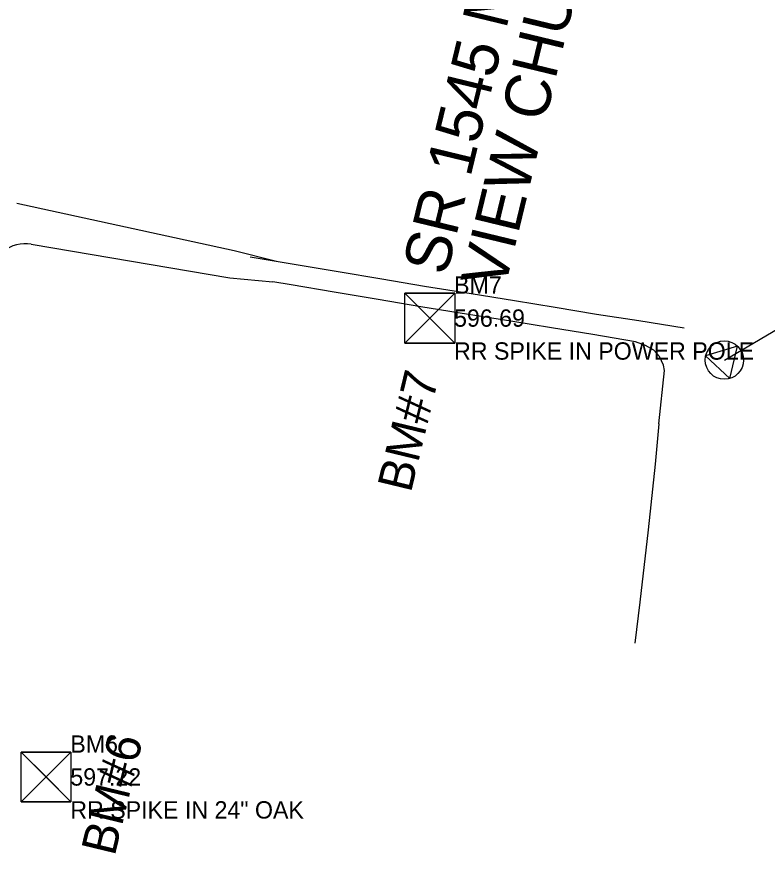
# Model space of a CAD drawing. Extents: x 1649669 to 1659218, y 588594 to 607900.
# Drawn here: x 1655167 to 1656033, y 600426 to 601392 of the extents above; entities that cross this region are included whole.
import ezdxf

# ---------------------------------------------------------------- set-up
doc = ezdxf.new("R2010")
doc.units = 0
for name, color, linetype in [('CTL Bench Mark CELL', 7, 'Continuous'), ('CTL Bench Mark Cogo Comment', 7, 'Continuous'), ('CTL Bench Mark Cogo Elevation', 7, 'Continuous'), ('CTL Bench Mark Cogo Number', 7, 'Continuous'), ('CTL Bench Mark Text', 7, 'Continuous'), ('CTL NGS Horizontal CELL', 7, 'Continuous'), ('CTL NGS Horizontal Leader', 7, 'Continuous'), ('Exist Roads EOP', 7, 'Continuous'), ('Sheet Data Field CELL', 7, 'Continuous')]:
    doc.layers.add(name, color=color, linetype=linetype)

# ---------------------------------------------------------------- blocks, each defined once
blk = doc.blocks.new('CTL NGS HORIZONTAL')
at = {"layer": 'CTL NGS Horizontal CELL'}
blk.add_line((0, 0), (0, 0), dxfattribs=at)
blk.add_lwpolyline([(-0.0638, -0.0372), (0.0638, -0.0372), (0, 0.0737), (-0.0638, -0.0372)], dxfattribs=at)
blk.add_circle((0, 0), 0.0738, dxfattribs=at)

msp = doc.modelspace()

# ---------------------------------------------------------------- linework, layer by layer
at = {"layer": 'CTL Bench Mark CELL'}
for p, q in [((1655643.59, 601043.97), (1655643.59, 601043.97)), ((1655200.64, 600514.48), (1655200.64, 600514.48))]:
    msp.add_line(p, q, dxfattribs=at)
for points in [[(1655614.79, 601072.67), (1655672.29, 601072.67), (1655672.29, 601015.17), (1655614.79, 601015.17)], [(1655171.84, 600543.18), (1655229.34, 600543.18), (1655229.34, 600485.68), (1655171.84, 600485.68)]]:
    msp.add_lwpolyline(points, close=True, dxfattribs=at)
for points in [[(1655672.29, 601072.67), (1655614.79, 601015.17), (1655643.54, 601043.92), (1655672.29, 601015.17), (1655614.79, 601072.67)], [(1655643.54, 601043.92), (1655672.29, 601072.67), (1655614.79, 601072.67), (1655643.54, 601043.92)], [(1655643.54, 601043.92), (1655614.79, 601015.17), (1655672.29, 601015.17), (1655643.54, 601043.92)], [(1655229.34, 600543.18), (1655171.84, 600485.68), (1655200.59, 600514.43), (1655229.34, 600485.68), (1655171.84, 600543.18)], [(1655200.59, 600514.43), (1655229.34, 600543.18), (1655171.84, 600543.18), (1655200.59, 600514.43)], [(1655200.59, 600514.43), (1655171.84, 600485.68), (1655229.34, 600485.68), (1655200.59, 600514.43)]]:
    msp.add_lwpolyline(points, dxfattribs=at)
at = {"layer": 'CTL NGS Horizontal Leader'}
msp.add_lwpolyline([(1655983.6, 600995.47), (1656243.85, 601148.6), (1656234.63, 601110.4)], dxfattribs=at)
at = {"layer": 'Exist Roads EOP'}
for p, q in [((1655166.87, 601176.61), (1655417.93, 601121.93)), ((1655183.46, 601129.18), (1655412.59, 601090.37)), ((1655417.93, 601121.92), (1655466.54, 601109.51)), ((1655436.39, 601114.75), (1655486.96, 601105.97)), ((1655486.96, 601105.97), (1655537.77, 601097.66)), ((1655537.77, 601097.66), (1655588.14, 601089.12)), ((1655412.59, 601090.37), (1655462.55, 601085.95)), ((1655483.44, 601082.33), (1655462.55, 601085.95)), ((1655533.01, 601073.9), (1655483.44, 601082.33)), ((1655588.14, 601089.12), (1655637.54, 601080.83)), ((1655637.54, 601080.83), (1655691.21, 601072.26)), ((1655584.06, 601065.32), (1655533.01, 601073.9)), ((1655691.21, 601072.26), (1655741.32, 601064.15)), ((1655633.1, 601056.94), (1655584.06, 601065.32)), ((1655741.32, 601064.15), (1655788.25, 601056.36)), ((1655688.16, 601048.1), (1655633.1, 601056.94)), ((1655788.25, 601056.36), (1655836, 601048.61)), ((1655737.3, 601040.21), (1655688.16, 601048.1)), ((1655836, 601048.61), (1655884.72, 601040.96)), ((1655783.97, 601032.62), (1655737.3, 601040.21)), ((1655831.74, 601024.99), (1655783.97, 601032.62)), ((1655884.72, 601040.96), (1655937.31, 601032.79)), ((1655881.18, 601016.56), (1655831.74, 601024.99)), ((1655892.38, 601012.38), (1655881.18, 601016.56)), ((1655902.32, 601006.82), (1655892.38, 601012.38)), ((1655908.74, 600999.72), (1655902.32, 601006.82)), ((1655913.45, 600989.49), (1655908.74, 600999.72)), ((1655914.61, 600983.35), (1655913.45, 600989.49)), ((1655907.78, 600922.03), (1655914.61, 600983.35)), ((1655907.78, 600922.03), (1655903.56, 600875.51)), ((1655903.56, 600875.51), (1655895.45, 600799.64)), ((1655895.45, 600799.64), (1655886.17, 600716.23)), ((1655886.17, 600716.23), (1655880.4, 600668.81))]:
    msp.add_line(p, q, dxfattribs=at)
msp.add_arc((1655176.61, 601088.75), 41, 80.3887, 176.00951, dxfattribs=at)

# ---------------------------------------------------------------- block references
at = {"layer": 'CTL NGS Horizontal CELL', "xscale": 300, "yscale": 300, "rotation": -42.96908576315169}
msp.add_blockref('CTL NGS HORIZONTAL', (1655983.6, 600995.47), dxfattribs=at)

# ---------------------------------------------------------------- texts
at = {"layer": 'CTL Bench Mark Cogo Comment'}
for s, p in [('RR SPIKE IN POWER POLE', (1655671.59, 600995.97)), ('RR SPIKE IN 24" OAK', (1655228.64, 600466.48))]:
    msp.add_text(s, height=20, dxfattribs=at).set_placement(p)
at = {"layer": 'CTL Bench Mark Cogo Elevation'}
for s, p in [('596.69', (1655671.59, 601033.97)), ('597.22', (1655228.64, 600504.48))]:
    msp.add_text(s, height=20, dxfattribs=at).set_placement(p)
at = {"layer": 'CTL Bench Mark Cogo Number'}
for s, p in [('BM7', (1655671.59, 601071.97)), ('BM6', (1655228.64, 600542.48))]:
    msp.add_text(s, height=20, dxfattribs=at).set_placement(p)
at = {"layer": 'CTL Bench Mark Text'}
for s, p in [('BM#7', (1655621.64, 600841.41)), ('BM#6', (1655279.75, 600422.16))]:
    msp.add_text(s, height=40, rotation=76.42607, dxfattribs=at).set_placement(p)
at = {"layer": 'Sheet Data Field CELL'}
for s, p in [('VIEW CHURCH ROAD', (1655729.79, 601075.46)), ('SR 1545 MOUNTAIN', (1655662.89, 601091.61))]:
    msp.add_text(s, height=52.5006, rotation=76.42607, dxfattribs=at).set_placement(p)

doc.saveas('drawing.dxf')
